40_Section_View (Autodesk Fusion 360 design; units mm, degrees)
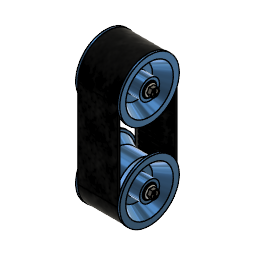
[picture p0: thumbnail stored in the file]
part number: 2026-07-20-09-32-54-680
description: Part Number
part number: 6656K105_Steel Ball Bearing
part number: 2026-07-20-09-37-17-004
part number: 2026-07-20-09-38-02-759
part number: 2026-07-20-09-41-52-306
part number: 98093A829_Black-Phosphate Class 10.9 Steel Hex Head Screw
sketch "Sketch1" plane through (0, 0, 0) normal (0, 1, 0) x axis (1, 0, 0)
  line L1 (50, 0) -> (-50, 0)
  line L2 (50, -10) -> (50, 0)
  line L3 (40, -10) -> (50, -10)
  line L4 (40, -12.5) -> (40, -10)
  line L5 (0, -12.5) -> (40, -12.5)
  line L6 (0, 0) -> (0, -12.5)
  line L7 (-50, -10) -> (-50, 0)
  line L8 (-40, -10) -> (-50, -10)
  line L9 (-40, -12.5) -> (-40, -10)
  line L10 (0, -12.5) -> (-40, -12.5)
  point P4 (0, 0)
  point P1 (0, 0)
  point P9 (0, 0)
  point P3 (50, 0)
  point P10 (-50, 0)
  point P5 (50, -10)
  point P11 (-50, -10)
  point P6 (40, -10)
  point P12 (-40, -10)
  point P7 (40, -12.5)
  point P13 (-40, -12.5)
  point P8 (0, -12.5)
  point P14 (0, -12.5)
  point P2 (-50, 0)
  midpoint L1 P4
  coincident P1 P4
  horizontal L1
  perpendicular L1 L2
  perpendicular L2 L3
  perpendicular L3 L4
  perpendicular L4 L5
  coincident P4 P9
  perpendicular L1 L6
  symmetric P3 L6 P10
  symmetric P5 L6 P11
  symmetric P6 L6 P12
  symmetric P7 L6 P13
  symmetric P8 L6 P14
  dimension "d1" distance P2 P3 = 100
  dimension "d2" = 20
  dimension "d3" = 25
  dimension "d4" distance P5 P6 = 10
revolve "Revolve1" sketch "Sketch1" AlongAngle 360
base_feature "Base Feature1"
copy_paste "CopyPaste1"
component_from_bodies "Body->Comp"
ground "Pin1"
as_built_joint "As-built1" OffsetX 0 OffsetY 0 OffsetZ 0 AngleZ 0
as_built_joint "As-built2" OffsetX 0 OffsetY 0 OffsetZ 0 AngleZ 0
sketch "Sketch1" plane through (0, 0, 0) normal (0, 1, 0) x axis (1, 0, 0)
  line L1 (50, 10) -> (50, -10)
  line L2 (40, 10) -> (50, 10)
  line L3 (40, 12.5) -> (40, 10)
  line L4 (-40, 12.5) -> (40, 12.5)
  line L5 (-40, 10) -> (-40, 12.5)
  line L6 (-50, 10) -> (-40, 10)
  line L7 (-50, -10) -> (-50, 10)
  line L8 (-40, -10) -> (-50, -10)
  line L9 (-40, -12.5) -> (-40, -10)
  line L10 (40, -12.5) -> (-40, -12.5)
  line L11 (40, -10) -> (40, -12.5)
  line L12 (50, -10) -> (40, -10)
  line L13 (49.5, 16) -> (50, 15.5)
  line L14 (40.5, 16) -> (49.5, 16)
  line L15 (40, 15.5) -> (40.5, 16)
  line L16 (40, 14.3333) -> (40, 15.5)
  line L17 (42.7778, 14.3333) -> (40, 14.3333)
  line L18 (50, 14.3333) -> (47.2222, 14.3333)
  line L19 (50, 15.5) -> (50, 14.3333)
  line L20 (50, -15.5) -> (49.5, -16)
  line L21 (50, -14.3333) -> (50, -15.5)
  line L22 (47.2222, -14.3333) -> (50, -14.3333)
  line L23 (40, -14.3333) -> (42.7778, -14.3333)
  line L24 (40, -15.5) -> (40, -14.3333)
  line L25 (40.5, -16) -> (40, -15.5)
  line L26 (49.5, -16) -> (40.5, -16)
  line L27 (-40.5, 16) -> (-40, 15.5)
  line L28 (-49.5, 16) -> (-40.5, 16)
  line L29 (-50, 15.5) -> (-49.5, 16)
  line L30 (-50, 14.3333) -> (-50, 15.5)
  line L31 (-47.2222, 14.3333) -> (-50, 14.3333)
  line L32 (-40, 14.3333) -> (-42.7778, 14.3333)
  line L33 (-40, 15.5) -> (-40, 14.3333)
  line L34 (-40, -15.5) -> (-40.5, -16)
  line L35 (-40, -14.3333) -> (-40, -15.5)
  line L36 (-42.7778, -14.3333) -> (-40, -14.3333)
  line L37 (-50, -14.3333) -> (-47.2222, -14.3333)
  line L38 (-50, -15.5) -> (-50, -14.3333)
  line L39 (-49.5, -16) -> (-50, -15.5)
  line L40 (-40.5, -16) -> (-49.5, -16)
  line L41 (50, -67.5) -> (50, -16)
  line L42 (45, -67.5) -> (50, -67.5)
  line L43 (45, -62.5) -> (45, -67.5)
  line L44 (23.3494, -50) -> (45, -62.5)
  line L45 (0, -50) -> (23.3494, -50)
  line L46 (0, -50) -> (0, 0)
  line L47 (40, -16) -> (50, -16)
  line L48 (40, -14.3333) -> (40, -16)
  line L49 (0, -14.3333) -> (40, -14.3333)
  line L50 (50, 0) -> (0, 0)
  line L51 (-40, -14.3333) -> (-40, -16)
  line L52 (-40, -16) -> (-50, -16)
  line L53 (-50, -67.5) -> (-50, -16)
  line L54 (-45, -67.5) -> (-50, -67.5)
  line L55 (-45, -62.5) -> (-45, -67.5)
  line L56 (-23.3494, -50) -> (-45, -62.5)
  line L57 (0, -50) -> (-23.3494, -50)
  line L58 (0, -14.3333) -> (-40, -14.3333)
  line L59 (20, -36.5192) -> (50, -53.8397)
  line L60 (20, -14.3333) -> (20, -36.5192)
  line L61 (-20, -36.5192) -> (-50, -53.8397)
  line L62 (-20, -14.3333) -> (-20, -36.5192)
  line L63 (-50, -22.5) -> (50, -22.5)
  arc A1 centre (45, 13) radius 2.5915 between (47.2222, 14.3333) and (42.7778, 14.3333)
  arc A2 centre (45, -13) radius 2.5915 between (42.7778, -14.3333) and (47.2222, -14.3333)
  arc A3 centre (-45, 13) radius 2.5915 between (-42.7778, 14.3333) and (-47.2222, 14.3333)
  arc A4 centre (-45, -13) radius 2.5915 between (-47.2222, -14.3333) and (-42.7778, -14.3333)
  point P1 (0, 0)
  point P56 (0, 0)
  point P29 (40, -14.3333)
  point P58 (40, -14.3333)
  point P59 (40, -14.3333)
  point P60 (0, -14.3333)
  point P61 (50, 0)
  point P23 (49.5, -16)
  point P50 (50, -16)
  point P64 (-50, -16)
  point P51 (50, -67.5)
  point P65 (-50, -67.5)
  point P52 (45, -67.5)
  point P66 (-45, -67.5)
  point P53 (45, -62.5)
  point P67 (-45, -62.5)
  point P54 (23.3494, -50)
  point P68 (-23.3494, -50)
  point P55 (0, -50)
  point P69 (0, -50)
  point P57 (40, -16)
  point P62 (-40, -16)
  point P63 (-40, -14.3333)
  point P70 (-40, -14.3333)
  point P71 (0, -14.3333)
  point P72 (50, -53.8397)
  point P74 (20, -14.3333)
  point P75 (-50, -53.8397)
  point P73 (20, -36.5192)
  point P76 (-20, -36.5192)
  point P77 (-20, -14.3333)
  point P78 (50, -22.5)
  point P79 (-50, -22.5)
  perpendicular L26 L41
  perpendicular L41 L42
  perpendicular L42 L43
  perpendicular L43 L45
  coincident P1 P56
  perpendicular L45 L46
  perpendicular L24 L47
  coincident P29 P58
  perpendicular L23 L48
  coincident P29 P59
  coincident L46 P60
  horizontal L49
  midpoint L1 P61
  collinear L21 L41
  coincident P23 L47
  symmetric P50 L46 P64
  symmetric P51 L46 P65
  symmetric P52 L46 P66
  symmetric P53 L46 P67
  symmetric P54 L46 P68
  symmetric P55 L46 P69
  symmetric L46 P57 P62
  symmetric L46 P58 P63
  symmetric L46 P59 P70
  symmetric L46 P60 P71
  coincident L41 P72
  parallel L44 L59
  coincident L49 P74
  vertical L60
  symmetric L46 P72 P75
  symmetric L46 P73 P76
  symmetric L46 P74 P77
  coincident L41 P78
  coincident L53 P79
  perpendicular L53 L63
  dimension "d14" = 135
  dimension "d15" distance P51 P52 = 5
  dimension "d16" distance P52 P53 = 5
  dimension "d17" angle L43 L44 = 60
  dimension "d18" = 100
  dimension "d19" distance L44 L59 = 10
  dimension "d20" = 40
  dimension "d21" = 45
revolve "Revolve1" sketch "Sketch1" AlongAngle 360
sketch "Sketch1" plane through (0, 0, 0) normal (1, 0, 0) x axis (0, 1, 0)
  line L1 (-67.5, -200) -> (-67.5, 0)
  line L2 (67.5, 0) -> (67.5, -200)
  arc A1 centre (0, -200) radius 67.5 clockwise from (67.5, -200) to (-67.5, -200)
  arc A2 centre (0, 0) radius 67.5 clockwise from (-67.5, 0) to (67.5, 0)
  point P1 (0, 0)
  point P2 (0, 0)
  point P6 (0, -200)
  coincident P1 P2
  vertical L1
  tangent L1 A1
  tangent L2 A2
  vertical L2
  tangent A1 L2
  tangent L1 A2
  dimension "d23" diameter A2 = 135
  dimension "d24" distance P2 P6 = 200
sketch "Sketch2" plane through (0, 0, 0) normal (0, 1, 0) x axis (1, 0, 0)
  line L1 (45, -62.5) -> (23.3494, -50)
  line L2 (23.3494, 50) -> (45, 62.5)
  line L3 (23.3494, -50) -> (-23.3494, -50)
  line L4 (-23.3494, 50) -> (23.3494, 50)
  line L5 (-23.3494, -50) -> (-45, -62.5)
  line L6 (-45, 62.5) -> (-23.3494, 50)
  line L7 (45, -67.5) -> (-45, -67.5)
  line L8 (45, -62.5) -> (45, -67.5)
  line L9 (-45, -62.5) -> (-45, -67.5)
  point P18 (-45, -67.5)
  point P19 (-45, -67.5)
  point P16 (45, -67.5)
  point P20 (45, -67.5)
  point P4 (45, -62.5)
  point P21 (45, -62.5)
  point P11 (-45, -62.5)
  point P22 (-45, -62.5)
  coincident P18 P19
  coincident P16 P20
  coincident P4 P21
  coincident P11 P22
sweep "Sweep1" sketch "Sketch2" TwistAngle 0 TaperAngle 0
sketch "Sketch3" plane through (0, 0, 0) normal (1, 0, 0) x axis (0, 1, 0)
  line L1 (-2.5, 47.5) -> (2.5, 47.5)
  line L2 (-2.5, 52.5) -> (-2.5, 47.5)
  line L3 (2.5, 52.5) -> (-2.5, 52.5)
  line L4 (2.5, 47.5) -> (2.5, 52.5)
  line L5 (-2.5, 52.5) -> (2.5, 47.5)
  line L6 (2.5, 52.5) -> (-2.5, 47.5)
  arc A1 centre (0, 0) radius 50 between (50, 0) and (-50, 0)
  point P9 (0, 50)
  point P7 (-2.5, 52.5)
  point P8 (2.5, 52.5)
  point P6 (-2.5, 47.5)
  horizontal L1
  perpendicular L1 L2
  parallel L1 L3
  parallel L2 L4
  coincident L5 P9
  coincident L6 P9
  midpoint A1 P9
  dimension "d31" distance P7 P8 = 5
  dimension "d32" distance P6 P7 = 5
extrude "Extrude1" cut sketch "Sketch3" profile of A1 L1 L2 L3 L4 no distance stored
path_pattern "PathPattern1" countU 70 PathPatternDelta 704.242
copy_paste "CopyPaste2"
copy_paste "CopyPaste3"
copy_paste "CopyPaste4"
copy_paste "CopyPaste5"
ground "Pin2"
as_built_joint "As-built3" OffsetX 0 OffsetY 0 OffsetZ 0 AngleZ 0
as_built_joint "As-built4" OffsetX 0 OffsetY 0 OffsetZ 0 AngleZ 0
as_built_joint "As-built5" OffsetX 0 OffsetY 0 OffsetZ 0 AngleZ 0
as_built_joint "As-built6" OffsetX 0 OffsetY 0 OffsetZ 0 AngleZ 0
ground "Pin3"
hole "Hole1" HoleDiameter 15 TipAngle 118
base_feature "Base Feature1"
joint "Assemble" alignAngle 180 alignOffsetX 0 alignOffsetY 0 alignOffsetZ 0
copy_paste "CopyPaste6"
joint "Assemble" alignAngle 180 alignOffsetX 0 alignOffsetY 0 alignOffsetZ 0
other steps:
base_feature "Base Feature1"
create_component "CreateComponent2"
create_component "CreateComponent3"
reparent_decal "ReparentDecal1"
remove_body "RemoveBody1"
create_component "CreateComponent4"
create_component "CreateComponent5"
create_component "CreateComponent6"
joint_origin "JointOrigin1"
joint_origin "JointOrigin1"
joint_origin "JointOrigin2"
joint_origin "JointOrigin2"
